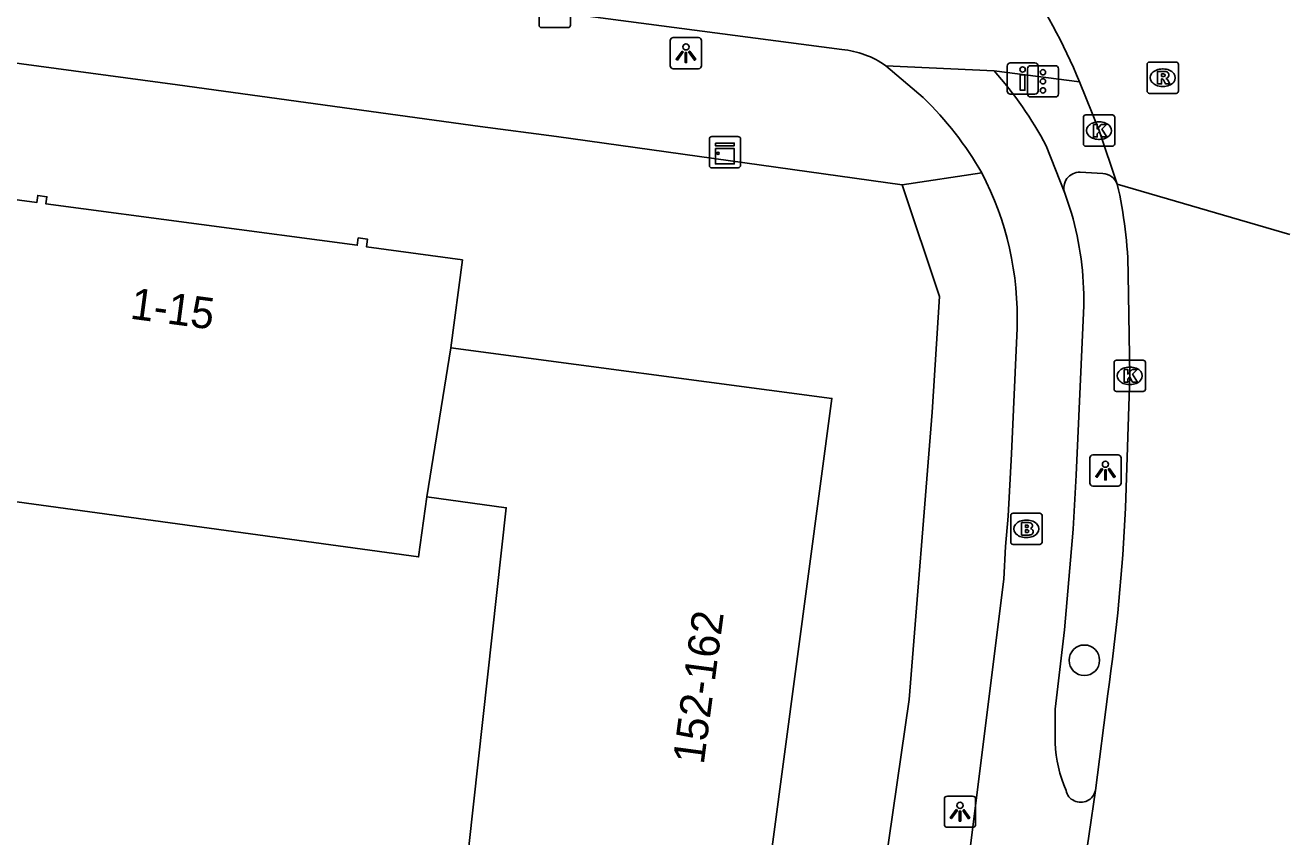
# Model space of a CAD drawing. Extents: x 161258 to 161838, y 380836 to 381727.
# Drawn here: x 161795.34 to 161835.77, y 381610.1 to 381636.05 of the extents above; entities that cross this region are included whole.
import ezdxf

# ---------------------------------------------------------------- set-up
doc = ezdxf.new("R2010")
doc.units = 0
for name, color, linetype in [('IMGEO_Boom', 7, 'Continuous'), ('IMGEO_Brandkraan', 7, 'Continuous'), ('IMGEO_Drukknoppaal', 7, 'Continuous'), ('IMGEO_Fietspad_open', 7, 'Continuous'), ('IMGEO_Kast', 7, 'Continuous'), ('IMGEO_Kolk', 7, 'Continuous'), ('IMGEO_Lichtpunt', 7, 'Continuous'), ('IMGEO_Pand', 7, 'Continuous'), ('IMGEO_Pand_nummerreeks', 7, 'Continuous'), ('IMGEO_Rijbaan_regionaal_gesloten', 7, 'Continuous'), ('IMGEO_Rioolput', 7, 'Continuous'), ('IMGEO_Verkeerseiland_open', 7, 'Continuous'), ('IMGEO_Verkeersregelinstallatiepaal', 7, 'Continuous'), ('IMGEO_Voetpad_open', 7, 'Continuous')]:
    doc.layers.add(name, color=color, linetype=linetype)

msp = doc.modelspace()

# ---------------------------------------------------------------- linework, layer by layer
at = {"layer": 'IMGEO_Boom'}
msp.add_circle((161829.206, 381615.743), 0.489, dxfattribs=at)
at = {"layer": 'IMGEO_Brandkraan'}
for p, q in [((161826.851, 381619.522), (161826.851, 381620.374)), ((161826.926, 381620.448), (161827.778, 381620.448)), ((161827.339, 381620.228), (161827.364, 381620.228)), ((161827.852, 381620.374), (161827.852, 381619.522)), ((161827.778, 381619.448), (161826.926, 381619.448)), ((161827.362, 381619.668), (161827.337, 381619.668))]:
    msp.add_line(p, q, dxfattribs=at)
for points in [[(161826.851, 381619.522), (161826.851, 381620.374)], [(161826.926, 381620.448), (161827.778, 381620.448)], [(161827.852, 381620.374), (161827.852, 381619.522)], [(161827.199, 381620.148), (161827.199, 381619.748), (161827.412, 381619.748)], [(161827.43, 381620.148), (161827.199, 381620.148)], [(161827.378, 381620.067), (161827.324, 381620.067), (161827.324, 381619.991)], [(161827.324, 381619.991), (161827.377, 381619.991)], [(161827.386, 381619.915), (161827.324, 381619.915), (161827.324, 381619.834)], [(161827.324, 381619.834), (161827.386, 381619.834)], [(161827.778, 381619.448), (161826.926, 381619.448)]]:
    msp.add_lwpolyline(points, dxfattribs=at)
for centre, radius, start, end in [((161826.928, 381620.372), 0.0765, 91.552, 178.448), ((161826.928, 381620.372), 0.0765, 91.552, 178.448), ((161827.776, 381620.372), 0.0765, 1.552, 88.448), ((161827.776, 381620.372), 0.0765, 1.552, 88.448), ((161827.379, 381620.029), 0.0379, 267.8285, 90.9355), ((161827.387, 381619.874), 0.0404, 269.8759, 90.5077), ((161827.434, 381620.003), 0.145, 59.4692, 91.5367), ((161827.459, 381620.05), 0.0922, 285.5137, 58.1501), ((161827.464, 381619.858), 0.105, 301.3115, 78.989), ((161826.928, 381619.524), 0.0765, 181.552, 268.448), ((161826.928, 381619.524), 0.0765, 181.552, 268.448), ((161827.418, 381619.999), 0.251, 268.6676, 293.5347), ((161827.776, 381619.524), 0.0765, 271.552, 358.448), ((161827.776, 381619.524), 0.0765, 271.552, 358.448)]:
    msp.add_arc(centre, radius, start, end, dxfattribs=at)
for centre, major_axis, ratio, start_param, end_param in [((161827.338, 381619.948), (-0.387, 0.002), 0.722429, 4.712389, 7.853982), ((161827.363, 381619.948), (-0.39, 0.002), 0.717154, 1.570796, 4.712389)]:
    msp.add_ellipse(centre, major_axis=major_axis, ratio=ratio, start_param=start_param, end_param=end_param, dxfattribs=at)
at = {"layer": 'IMGEO_Drukknoppaal'}
for p, q in [((161826.837, 381634.85), (161827.627, 381634.85)), ((161827.627, 381634.85), (161826.837, 381634.85)), ((161826.737, 381633.95), (161826.737, 381634.75)), ((161826.737, 381634.75), (161826.737, 381633.95)), ((161827.727, 381634.75), (161827.727, 381633.95)), ((161827.727, 381633.95), (161827.727, 381634.75)), ((161827.627, 381633.85), (161826.837, 381633.85)), ((161826.837, 381633.85), (161827.627, 381633.85))]:
    msp.add_line(p, q, dxfattribs=at)
msp.add_lwpolyline([(161827.307, 381634.475), (161827.307, 381633.975), (161827.157, 381633.975), (161827.157, 381634.475), (161827.307, 381634.475)], dxfattribs=at)
msp.add_circle((161827.232, 381634.64), 0.085, dxfattribs=at)
for centre, start, end in [((161826.837, 381634.75), 90, 180), ((161826.837, 381634.75), 90, 180), ((161827.627, 381634.75), 0, 90), ((161827.627, 381634.75), 360, 90), ((161826.837, 381633.95), 180, 270), ((161826.837, 381633.95), 180, 270), ((161827.627, 381633.95), 270, 0), ((161827.627, 381633.95), 270, 0)]:
    msp.add_arc(centre, 0.1, start, end, dxfattribs=at)
at = {"layer": 'IMGEO_Fietspad_open'}
for points in [[(161756.215, 381644.03), (161759.426, 381643.601), (161782.848, 381640.443), (161812.273, 381636.483), (161821.453, 381635.279)], [(161822.858, 381634.761), (161826.32, 381634.599)], [(161824.056, 381633.743), (161822.858, 381634.761)], [(161826.32, 381634.599), (161829.056, 381634.244)], [(161827.987, 381632.196), (161828.579, 381630.688)], [(161828.8, 381630.049), (161828.579, 381630.688)], [(161828.276, 381613.099), (161828.276, 381614.175), (161828.576, 381616.717), (161828.849, 381619.936), (161828.949, 381621.661), (161829.188, 381627.089)], [(161825.416, 381608.661), (161825.561, 381609.817), (161826.631, 381618.339), (161826.687, 381619.38), (161826.771, 381620.35), (161826.88, 381622.35), (161827.053, 381626.363)]]:
    msp.add_lwpolyline(points, dxfattribs=at)
for centre, radius, start, end in [((161821.182, 381632.38), 2.912, 54.8616, 84.6622), ((161817.087, 381626.415), 12.338, 27.943, 41.5564), ((161816.124, 381625.657), 11.327, 30.0841, 45.5505), ((161817.11, 381626.721), 9.949, 357.9363, 27.6284), ((161818.716, 381627.222), 10.473, 359.2735, 15.6621), ((161832.39, 381613.235), 4.116, 181.8894, 203.7028), ((161829.039, 381611.646), 0.424, 188.9747, 248.4726), ((161829.095, 381611.678), 0.475, 243.6739, 347.3979)]:
    msp.add_arc(centre, radius, start, end, dxfattribs=at)
at = {"layer": 'IMGEO_Kast'}
for p, q in [((161817.215, 381631.571), (161817.215, 381632.412)), ((161817.215, 381632.412), (161817.215, 381631.571)), ((161817.29, 381632.496), (161818.131, 381632.496)), ((161818.131, 381632.496), (161817.29, 381632.496)), ((161818.215, 381632.421), (161818.215, 381631.58)), ((161818.215, 381631.58), (161818.215, 381632.421)), ((161818.14, 381631.496), (161817.299, 381631.496)), ((161817.299, 381631.496), (161818.14, 381631.496))]:
    msp.add_line(p, q, dxfattribs=at)
for points in [[(161817.41, 381632.286), (161818.01, 381632.286), (161818.01, 381632.201), (161817.41, 381632.201), (161817.41, 381632.286)], [(161817.41, 381632.111), (161818.01, 381632.111), (161818.01, 381631.622), (161817.41, 381631.622), (161817.41, 381632.111)]]:
    msp.add_lwpolyline(points, dxfattribs=at)
msp.add_circle((161817.494, 381631.96), 0.0377, dxfattribs=at)
for centre, start, end in [((161817.293, 381632.418), 92.4484, 184.2845), ((161817.293, 381632.418), 92.4484, 184.2845), ((161818.137, 381632.418), 2.4484, 94.2845), ((161818.137, 381632.418), 2.4484, 94.2845), ((161817.293, 381631.574), 182.4484, 274.2845), ((161817.293, 381631.574), 182.4484, 274.2845), ((161818.137, 381631.574), 272.4484, 4.2845), ((161818.137, 381631.574), 272.4484, 4.2845)]:
    msp.add_arc(centre, 0.0779, start, end, dxfattribs=at)
at = {"layer": 'IMGEO_Kolk'}
for p, q in [((161811.772, 381636.055), (161811.772, 381636.907)), ((161812.773, 381636.907), (161812.773, 381636.055)), ((161812.699, 381635.981), (161811.847, 381635.981)), ((161829.25, 381633.186), (161830.102, 381633.186)), ((161829.175, 381632.26), (161829.175, 381633.112)), ((161829.663, 381632.966), (161829.688, 381632.966)), ((161830.176, 381633.112), (161830.176, 381632.26)), ((161829.686, 381632.406), (161829.661, 381632.406)), ((161830.102, 381632.186), (161829.25, 381632.186)), ((161830.157, 381624.417), (161830.157, 381625.269)), ((161830.232, 381625.343), (161831.084, 381625.343)), ((161830.645, 381625.123), (161830.67, 381625.123)), ((161831.158, 381625.269), (161831.158, 381624.417)), ((161831.084, 381624.343), (161830.232, 381624.343)), ((161830.668, 381624.563), (161830.643, 381624.563))]:
    msp.add_line(p, q, dxfattribs=at)
for points in [[(161811.772, 381636.055), (161811.772, 381636.907)], [(161812.773, 381636.907), (161812.773, 381636.055)], [(161812.699, 381635.981), (161811.847, 381635.981)], [(161829.25, 381633.186), (161830.102, 381633.186)], [(161829.175, 381632.26), (161829.175, 381633.112)], [(161829.496, 381632.886), (161829.619, 381632.886), (161829.619, 381632.735), (161829.749, 381632.886), (161829.913, 381632.886), (161829.767, 381632.735), (161829.92, 381632.486), (161829.768, 381632.486), (161829.683, 381632.65), (161829.619, 381632.583), (161829.619, 381632.486), (161829.496, 381632.486), (161829.496, 381632.886)], [(161830.176, 381633.112), (161830.176, 381632.26)], [(161830.102, 381632.186), (161829.25, 381632.186)], [(161830.157, 381624.417), (161830.157, 381625.269)], [(161830.232, 381625.343), (161831.084, 381625.343)], [(161831.158, 381625.269), (161831.158, 381624.417)], [(161830.478, 381625.043), (161830.601, 381625.043), (161830.601, 381624.892), (161830.731, 381625.043), (161830.895, 381625.043), (161830.749, 381624.892), (161830.902, 381624.643), (161830.75, 381624.643), (161830.665, 381624.807), (161830.601, 381624.74), (161830.601, 381624.643), (161830.478, 381624.643), (161830.478, 381625.043)], [(161831.084, 381624.343), (161830.232, 381624.343)]]:
    msp.add_lwpolyline(points, dxfattribs=at)
for centre, start, end in [((161811.849, 381636.057), 181.552, 268.448), ((161811.849, 381636.057), 181.552, 268.448), ((161812.697, 381636.057), 271.552, 358.448), ((161812.697, 381636.057), 271.552, 358.448), ((161829.252, 381633.11), 91.552, 178.448), ((161829.252, 381633.11), 91.552, 178.448), ((161830.1, 381633.11), 1.552, 88.448), ((161830.1, 381633.11), 1.552, 88.448), ((161829.252, 381632.262), 181.552, 268.448), ((161829.252, 381632.262), 181.552, 268.448), ((161830.1, 381632.262), 271.552, 358.448), ((161830.1, 381632.262), 271.552, 358.448), ((161830.234, 381625.267), 91.552, 178.448), ((161830.234, 381625.267), 91.552, 178.448), ((161831.082, 381625.267), 1.552, 88.448), ((161831.082, 381625.267), 1.552, 88.448), ((161830.234, 381624.419), 181.552, 268.448), ((161830.234, 381624.419), 181.552, 268.448), ((161831.082, 381624.419), 271.552, 358.448), ((161831.082, 381624.419), 271.552, 358.448)]:
    msp.add_arc(centre, 0.0765, start, end, dxfattribs=at)
for centre, major_axis, ratio, start_param, end_param in [((161829.662, 381632.686), (-0.387, 0.002), 0.722429, 4.712389, 7.853982), ((161829.687, 381632.686), (-0.39, 0.002), 0.717154, 1.570796, 4.712389), ((161830.644, 381624.843), (-0.387, 0.002), 0.722429, 4.712389, 7.853982), ((161830.669, 381624.843), (-0.39, 0.002), 0.717154, 1.570796, 4.712389)]:
    msp.add_ellipse(centre, major_axis=major_axis, ratio=ratio, start_param=start_param, end_param=end_param, dxfattribs=at)
at = {"layer": 'IMGEO_Lichtpunt'}
for p, q in [((161816.869, 381635.661), (161816.061, 381635.661)), ((161816.869, 381635.661), (161816.061, 381635.661)), ((161815.967, 381635.566), (161815.967, 381634.759)), ((161815.967, 381635.566), (161815.967, 381634.759)), ((161816.963, 381634.759), (161816.963, 381635.566)), ((161816.963, 381634.759), (161816.963, 381635.566)), ((161816.061, 381634.665), (161816.869, 381634.665)), ((161816.061, 381634.665), (161816.869, 381634.665)), ((161830.284, 381622.312), (161829.476, 381622.312)), ((161830.284, 381622.312), (161829.476, 381622.312)), ((161829.382, 381622.217), (161829.382, 381621.41)), ((161829.382, 381622.217), (161829.382, 381621.41)), ((161830.378, 381621.41), (161830.378, 381622.217)), ((161830.378, 381621.41), (161830.378, 381622.217)), ((161829.476, 381621.316), (161830.284, 381621.316)), ((161829.476, 381621.316), (161830.284, 381621.316)), ((161825.634, 381611.399), (161824.826, 381611.399)), ((161825.634, 381611.399), (161824.826, 381611.399)), ((161824.732, 381611.304), (161824.732, 381610.497)), ((161824.732, 381611.304), (161824.732, 381610.497)), ((161825.728, 381610.497), (161825.728, 381611.304)), ((161825.728, 381610.497), (161825.728, 381611.304)), ((161824.826, 381610.403), (161825.634, 381610.403)), ((161824.826, 381610.403), (161825.634, 381610.403))]:
    msp.add_line(p, q, dxfattribs=at)
for points in [[(161816.341, 381635.23), (161816.38, 381635.202), (161816.192, 381634.94), (161816.154, 381634.967), (161816.341, 381635.23)], [(161816.443, 381635.182), (161816.49, 381635.182), (161816.49, 381634.86), (161816.443, 381634.86), (161816.443, 381635.182)], [(161816.553, 381635.202), (161816.591, 381635.229), (161816.778, 381634.967), (161816.739, 381634.939), (161816.553, 381635.202)], [(161829.756, 381621.881), (161829.795, 381621.853), (161829.607, 381621.591), (161829.569, 381621.618), (161829.756, 381621.881)], [(161829.968, 381621.853), (161830.006, 381621.88), (161830.193, 381621.618), (161830.154, 381621.59), (161829.968, 381621.853)], [(161829.858, 381621.833), (161829.905, 381621.833), (161829.905, 381621.511), (161829.858, 381621.511), (161829.858, 381621.833)], [(161825.106, 381610.968), (161825.145, 381610.94), (161824.957, 381610.678), (161824.919, 381610.705), (161825.106, 381610.968)], [(161825.318, 381610.94), (161825.356, 381610.967), (161825.543, 381610.705), (161825.504, 381610.677), (161825.318, 381610.94)], [(161825.208, 381610.92), (161825.255, 381610.92), (161825.255, 381610.598), (161825.208, 381610.598), (161825.208, 381610.92)]]:
    msp.add_lwpolyline(points, dxfattribs=at)
for centre in [(161816.466, 381635.364), (161829.881, 381622.015), (161825.231, 381611.102)]:
    msp.add_circle(centre, 0.0994, dxfattribs=at)
for centre, start, end in [((161816.061, 381635.566), 90, 180), ((161816.061, 381635.566), 90, 180), ((161816.869, 381635.566), 0, 90), ((161816.869, 381635.566), 0, 90), ((161816.061, 381634.759), 180, 270), ((161816.061, 381634.759), 180, 270), ((161816.869, 381634.759), 270, 0), ((161816.869, 381634.759), 270, 360), ((161829.476, 381622.217), 90, 180), ((161829.476, 381622.217), 90, 180), ((161830.284, 381622.217), 0, 90), ((161830.284, 381622.217), 0, 90), ((161829.476, 381621.41), 180, 270), ((161829.476, 381621.41), 180, 270), ((161830.284, 381621.41), 270, 0), ((161830.284, 381621.41), 270, 360), ((161824.826, 381611.304), 90, 180), ((161824.826, 381611.304), 90, 180), ((161825.634, 381611.304), 0, 90), ((161825.634, 381611.304), 0, 90), ((161824.826, 381610.497), 180, 270), ((161824.826, 381610.497), 180, 270), ((161825.634, 381610.497), 270, 0), ((161825.634, 381610.497), 270, 360)]:
    msp.add_arc(centre, 0.0946, start, end, dxfattribs=at)
at = {"layer": 'IMGEO_Pand'}
for points in [[(161792.775, 381630.786), (161795.709, 381630.385), (161795.739, 381630.612), (161796.034, 381630.572), (161796.003, 381630.342), (161805.958, 381629.018), (161805.989, 381629.251), (161806.285, 381629.211), (161806.253, 381628.967), (161809.318, 381628.548), (161808.945, 381625.742)], [(161808.945, 381625.742), (161821.137, 381624.12), (161818.877, 381607.129), (161813.924, 381607.807), (161809.378, 381608.434), (161810.722, 381620.621), (161808.179, 381620.968)], [(161808.945, 381625.742), (161808.179, 381620.968)], [(161808.179, 381620.968), (161807.917, 381619.051), (161791.477, 381621.299)]]:
    msp.add_lwpolyline(points, dxfattribs=at)
at = {"layer": 'IMGEO_Rijbaan_regionaal_gesloten'}
for points in [[(161829.056, 381634.244), (161829.677, 381632.687), (161830.258, 381630.974)], [(161835.772, 381629.362), (161830.258, 381630.974)], [(161830.611, 381628.07), (161830.66, 381624.843), (161830.523, 381620.607)], [(161829.955, 381614.672), (161829.558, 381611.574)], [(161829.558, 381611.574), (161828.749, 381606.032)]]:
    msp.add_lwpolyline(points, dxfattribs=at)
for centre, radius, start, end in [((161809.085, 381625.794), 21.685, 22.9337, 33.4371), ((161816.687, 381627.851), 13.926, 0.9017, 12.9596), ((161769.09, 381623.492), 61.5, 351.7549, 357.31159)]:
    msp.add_arc(centre, radius, start, end, dxfattribs=at)
at = {"layer": 'IMGEO_Rioolput'}
for p, q in [((161831.213, 381633.952), (161831.213, 381634.804)), ((161831.288, 381634.878), (161832.14, 381634.878)), ((161832.214, 381634.804), (161832.214, 381633.952)), ((161831.701, 381634.658), (161831.726, 381634.658)), ((161831.724, 381634.098), (161831.699, 381634.098)), ((161832.14, 381633.878), (161831.288, 381633.878))]:
    msp.add_line(p, q, dxfattribs=at)
for points in [[(161831.213, 381633.952), (161831.213, 381634.804)], [(161831.288, 381634.878), (161832.14, 381634.878)], [(161832.214, 381634.804), (161832.214, 381633.952)], [(161831.802, 381634.576), (161831.55, 381634.578), (161831.55, 381634.178)], [(161831.728, 381634.497), (161831.674, 381634.497), (161831.674, 381634.416)], [(161831.674, 381634.416), (161831.726, 381634.416)], [(161831.55, 381634.178), (161831.674, 381634.178), (161831.674, 381634.34), (161831.685, 381634.34)], [(161831.732, 381634.311), (161831.803, 381634.178), (161831.943, 381634.178), (161831.878, 381634.304)], [(161832.14, 381633.878), (161831.288, 381633.878)]]:
    msp.add_lwpolyline(points, dxfattribs=at)
for centre, radius, start, end in [((161831.29, 381634.802), 0.0765, 91.552, 178.448), ((161831.29, 381634.802), 0.0765, 91.552, 178.448), ((161832.138, 381634.802), 0.0765, 1.552, 88.448), ((161832.138, 381634.802), 0.0765, 1.552, 88.448), ((161831.71, 381634.605), 0.19, 274.7715, 282.9687), ((161831.734, 381634.401), 0.0964, 77.0061, 93.1865), ((161831.748, 381634.458), 0.0378, 276.6634, 79.6772), ((161831.801, 381634.466), 0.109, 350.3612, 89.416), ((161831.799, 381634.466), 0.112, 277.5842, 350.9817), ((161831.684, 381634.287), 0.0533, 26.0293, 88.6989), ((161831.783, 381634.251), 0.108, 29.5134, 73.7905), ((161831.29, 381633.954), 0.0765, 181.552, 268.448), ((161831.29, 381633.954), 0.0765, 181.552, 268.448), ((161832.138, 381633.954), 0.0765, 271.552, 358.448), ((161832.138, 381633.954), 0.0765, 271.552, 358.448)]:
    msp.add_arc(centre, radius, start, end, dxfattribs=at)
for centre, major_axis, ratio, start_param, end_param in [((161831.7, 381634.378), (-0.387, 0.002), 0.722429, 4.712389, 7.853982), ((161831.725, 381634.378), (-0.39, 0.002), 0.717154, 1.570796, 4.712389)]:
    msp.add_ellipse(centre, major_axis=major_axis, ratio=ratio, start_param=start_param, end_param=end_param, dxfattribs=at)
at = {"layer": 'IMGEO_Verkeerseiland_open'}
msp.add_lwpolyline([(161829.067, 381631.357), (161829.8, 381631.313)], dxfattribs=at)
for centre, radius, start, end in [((161829.06, 381630.85), 0.507, 89.1568, 198.6257), ((161829.77, 381630.793), 0.521, 20.3396, 86.6446)]:
    msp.add_arc(centre, radius, start, end, dxfattribs=at)
at = {"layer": 'IMGEO_Verkeersregelinstallatiepaal'}
for p, q in [((161827.387, 381633.862), (161827.387, 381634.662)), ((161827.387, 381634.662), (161827.387, 381633.862)), ((161827.487, 381634.762), (161828.277, 381634.762)), ((161828.277, 381634.762), (161827.487, 381634.762)), ((161828.377, 381634.662), (161828.377, 381633.862)), ((161828.377, 381633.862), (161828.377, 381634.662)), ((161828.277, 381633.762), (161827.487, 381633.762)), ((161827.487, 381633.762), (161828.277, 381633.762))]:
    msp.add_line(p, q, dxfattribs=at)
for centre in [(161827.882, 381634.552), (161827.882, 381634.262), (161827.882, 381633.972)]:
    msp.add_circle(centre, 0.085, dxfattribs=at)
for centre, start, end in [((161827.487, 381634.662), 90, 180), ((161827.487, 381634.662), 90, 180), ((161828.277, 381634.662), 0, 90), ((161828.277, 381634.662), 360, 90), ((161827.487, 381633.862), 180, 270), ((161827.487, 381633.862), 180, 270), ((161828.277, 381633.862), 270, 0), ((161828.277, 381633.862), 270, 0)]:
    msp.add_arc(centre, 0.1, start, end, dxfattribs=at)
at = {"layer": 'IMGEO_Voetpad_open'}
for points in [[(161823.38, 381630.949), (161812.33, 381632.493), (161809.891, 381632.818), (161800.213, 381634.153), (161755.234, 381640.215)], [(161823.38, 381630.949), (161825.925, 381631.335)], [(161807.78, 381535.827), (161808.863, 381536.294), (161809.558, 381536.593), (161821.924, 381602.839), (161823.603, 381614.49), (161824.336, 381623.682), (161824.572, 381627.383), (161823.38, 381630.949)]]:
    msp.add_lwpolyline(points, dxfattribs=at)

# ---------------------------------------------------------------- texts
at = {"layer": 'IMGEO_Pand_nummerreeks'}
for s, rotation, p in [('1-15', 352.4275, (161798.665, 381626.675)), ('152-162', 82.4235, (161817.034, 381612.388))]:
    msp.add_text(s, height=1, rotation=rotation, dxfattribs=at).set_placement(p)

doc.saveas('drawing.dxf')
